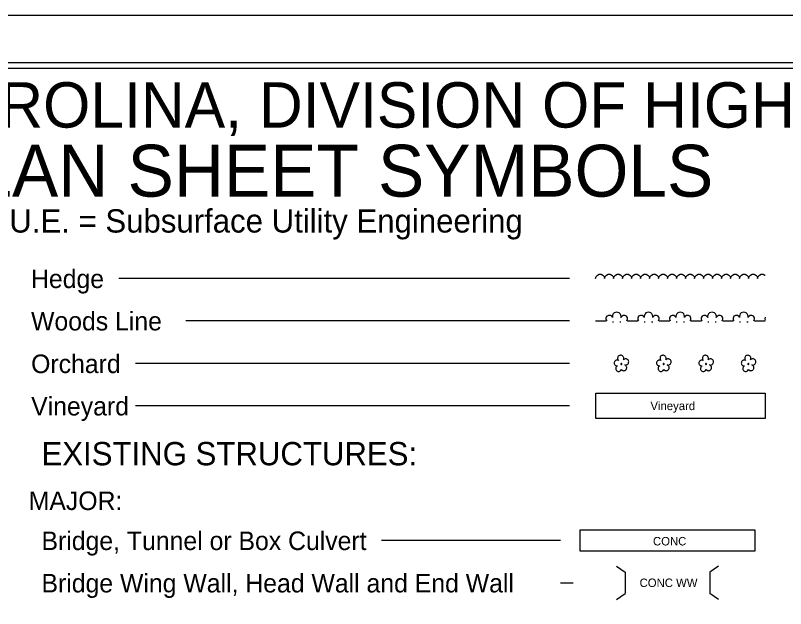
# Model space of a CAD drawing. Extents: x 1578579.3 to 1578613, y 915799 to 915821.
# Drawn here: x 1578597.74 to 1578605.02, y 915815.36 to 915820.96 of the extents above; entities that cross this region are included whole.
import ezdxf

# ---------------------------------------------------------------- set-up
doc = ezdxf.new("R2010")
doc.units = 0
for name, color, linetype in [('Sheet Cutting Line CELL', 7, 'Continuous'), ('Sheet Plot Border Inside CELL', 7, 'Continuous'), ('Sheet Plot Border Outside CELL', 7, 'Continuous'), ('Sheet Symbology CELL', 7, 'Continuous')]:
    doc.layers.add(name, color=color, linetype=linetype)

msp = doc.modelspace()

# ---------------------------------------------------------------- linework, layer by layer
at = {"layer": 'Sheet Cutting Line CELL'}
msp.add_line((1578612.9696, 915820.9627), (1578579.2896, 915820.9627), dxfattribs=at)
at = {"layer": 'Sheet Plot Border Inside CELL'}
msp.add_lwpolyline([(1578579.5496, 915799.4117), (1578612.8796, 915799.4117), (1578612.8796, 915820.5137), (1578579.5496, 915820.5137)], close=True, dxfattribs=at)
at = {"layer": 'Sheet Plot Border Outside CELL'}
msp.add_lwpolyline([(1578579.2896, 915798.9627), (1578612.9696, 915798.9627), (1578612.9696, 915820.9627), (1578579.2896, 915820.9627)], close=True, dxfattribs=at)
at = {"layer": 'Sheet Symbology CELL'}
for p, q in [((1578602.9751, 915818.4797), (1578598.7214, 915818.4797)), ((1578603.223, 915818.4797), (1578603.229, 915818.4987)), ((1578603.229, 915818.4987), (1578603.241, 915818.5117)), ((1578603.241, 915818.5117), (1578603.257, 915818.5207)), ((1578603.257, 915818.5207), (1578603.276, 915818.5207)), ((1578603.276, 915818.5207), (1578603.292, 915818.5107)), ((1578603.292, 915818.5107), (1578603.303, 915818.4977)), ((1578603.303, 915818.4977), (1578603.307, 915818.4807)), ((1578603.308, 915818.4797), (1578603.314, 915818.4987)), ((1578603.314, 915818.4987), (1578603.326, 915818.5117)), ((1578603.326, 915818.5117), (1578603.342, 915818.5207)), ((1578603.342, 915818.5207), (1578603.361, 915818.5207)), ((1578603.361, 915818.5207), (1578603.377, 915818.5107)), ((1578603.377, 915818.5107), (1578603.388, 915818.4977)), ((1578603.388, 915818.4977), (1578603.392, 915818.4807)), ((1578603.393, 915818.4797), (1578603.399, 915818.4987)), ((1578603.399, 915818.4987), (1578603.411, 915818.5117)), ((1578603.411, 915818.5117), (1578603.427, 915818.5207)), ((1578603.427, 915818.5207), (1578603.446, 915818.5207)), ((1578603.446, 915818.5207), (1578603.462, 915818.5107)), ((1578603.462, 915818.5107), (1578603.473, 915818.4977)), ((1578603.473, 915818.4977), (1578603.477, 915818.4807)), ((1578603.478, 915818.4797), (1578603.484, 915818.4987)), ((1578603.484, 915818.4987), (1578603.496, 915818.5117)), ((1578603.496, 915818.5117), (1578603.512, 915818.5207)), ((1578603.512, 915818.5207), (1578603.531, 915818.5207)), ((1578603.531, 915818.5207), (1578603.547, 915818.5107)), ((1578603.547, 915818.5107), (1578603.558, 915818.4977)), ((1578603.558, 915818.4977), (1578603.562, 915818.4807)), ((1578603.563, 915818.4797), (1578603.569, 915818.4987)), ((1578603.569, 915818.4987), (1578603.581, 915818.5117)), ((1578603.581, 915818.5117), (1578603.597, 915818.5207)), ((1578603.597, 915818.5207), (1578603.616, 915818.5207)), ((1578603.616, 915818.5207), (1578603.632, 915818.5107)), ((1578603.632, 915818.5107), (1578603.643, 915818.4977)), ((1578603.643, 915818.4977), (1578603.647, 915818.4807)), ((1578603.648, 915818.4797), (1578603.654, 915818.4987)), ((1578603.654, 915818.4987), (1578603.666, 915818.5117)), ((1578603.666, 915818.5117), (1578603.682, 915818.5207)), ((1578603.682, 915818.5207), (1578603.701, 915818.5207)), ((1578603.701, 915818.5207), (1578603.717, 915818.5107)), ((1578603.717, 915818.5107), (1578603.728, 915818.4977)), ((1578603.728, 915818.4977), (1578603.732, 915818.4807)), ((1578603.733, 915818.4797), (1578603.739, 915818.4987)), ((1578603.739, 915818.4987), (1578603.751, 915818.5117)), ((1578603.751, 915818.5117), (1578603.767, 915818.5207)), ((1578603.767, 915818.5207), (1578603.786, 915818.5207)), ((1578603.786, 915818.5207), (1578603.802, 915818.5107)), ((1578603.802, 915818.5107), (1578603.813, 915818.4977)), ((1578603.813, 915818.4977), (1578603.817, 915818.4807)), ((1578603.818, 915818.4797), (1578603.824, 915818.4987)), ((1578603.824, 915818.4987), (1578603.836, 915818.5117)), ((1578603.836, 915818.5117), (1578603.852, 915818.5207)), ((1578603.852, 915818.5207), (1578603.871, 915818.5207)), ((1578603.871, 915818.5207), (1578603.887, 915818.5107)), ((1578603.887, 915818.5107), (1578603.898, 915818.4977)), ((1578603.898, 915818.4977), (1578603.902, 915818.4807)), ((1578603.903, 915818.4797), (1578603.909, 915818.4987)), ((1578603.909, 915818.4987), (1578603.921, 915818.5117)), ((1578603.921, 915818.5117), (1578603.937, 915818.5207)), ((1578603.937, 915818.5207), (1578603.956, 915818.5207)), ((1578603.956, 915818.5207), (1578603.972, 915818.5107)), ((1578603.972, 915818.5107), (1578603.983, 915818.4977)), ((1578603.983, 915818.4977), (1578603.987, 915818.4807)), ((1578603.988, 915818.4797), (1578603.994, 915818.4987)), ((1578603.994, 915818.4987), (1578604.006, 915818.5117)), ((1578604.006, 915818.5117), (1578604.022, 915818.5207)), ((1578604.022, 915818.5207), (1578604.041, 915818.5207)), ((1578604.041, 915818.5207), (1578604.057, 915818.5107)), ((1578604.057, 915818.5107), (1578604.068, 915818.4977)), ((1578604.068, 915818.4977), (1578604.072, 915818.4807)), ((1578604.073, 915818.4797), (1578604.079, 915818.4987)), ((1578604.079, 915818.4987), (1578604.091, 915818.5117)), ((1578604.091, 915818.5117), (1578604.107, 915818.5207)), ((1578604.107, 915818.5207), (1578604.126, 915818.5207)), ((1578604.126, 915818.5207), (1578604.142, 915818.5107)), ((1578604.142, 915818.5107), (1578604.153, 915818.4977)), ((1578604.153, 915818.4977), (1578604.157, 915818.4807)), ((1578604.158, 915818.4797), (1578604.164, 915818.4987)), ((1578604.164, 915818.4987), (1578604.176, 915818.5117)), ((1578604.176, 915818.5117), (1578604.192, 915818.5207)), ((1578604.192, 915818.5207), (1578604.211, 915818.5207)), ((1578604.211, 915818.5207), (1578604.227, 915818.5107)), ((1578604.227, 915818.5107), (1578604.238, 915818.4977)), ((1578604.238, 915818.4977), (1578604.242, 915818.4807)), ((1578604.243, 915818.4797), (1578604.249, 915818.4987)), ((1578604.249, 915818.4987), (1578604.261, 915818.5117)), ((1578604.261, 915818.5117), (1578604.277, 915818.5207)), ((1578604.277, 915818.5207), (1578604.296, 915818.5207)), ((1578604.296, 915818.5207), (1578604.312, 915818.5107)), ((1578604.312, 915818.5107), (1578604.323, 915818.4977)), ((1578604.323, 915818.4977), (1578604.327, 915818.4807)), ((1578604.328, 915818.4797), (1578604.334, 915818.4987)), ((1578604.334, 915818.4987), (1578604.346, 915818.5117)), ((1578604.346, 915818.5117), (1578604.362, 915818.5207)), ((1578604.362, 915818.5207), (1578604.381, 915818.5207)), ((1578604.381, 915818.5207), (1578604.397, 915818.5107)), ((1578604.397, 915818.5107), (1578604.408, 915818.4977)), ((1578604.408, 915818.4977), (1578604.412, 915818.4807)), ((1578604.413, 915818.4797), (1578604.419, 915818.4987)), ((1578604.419, 915818.4987), (1578604.431, 915818.5117)), ((1578604.431, 915818.5117), (1578604.447, 915818.5207)), ((1578604.447, 915818.5207), (1578604.466, 915818.5207)), ((1578604.466, 915818.5207), (1578604.482, 915818.5107)), ((1578604.482, 915818.5107), (1578604.493, 915818.4977)), ((1578604.493, 915818.4977), (1578604.497, 915818.4807)), ((1578604.498, 915818.4797), (1578604.504, 915818.4987)), ((1578604.504, 915818.4987), (1578604.516, 915818.5117)), ((1578604.516, 915818.5117), (1578604.532, 915818.5207)), ((1578604.532, 915818.5207), (1578604.551, 915818.5207)), ((1578604.551, 915818.5207), (1578604.567, 915818.5107)), ((1578604.567, 915818.5107), (1578604.578, 915818.4977)), ((1578604.578, 915818.4977), (1578604.582, 915818.4807)), ((1578604.583, 915818.4797), (1578604.589, 915818.4987)), ((1578604.589, 915818.4987), (1578604.601, 915818.5117)), ((1578604.601, 915818.5117), (1578604.617, 915818.5207)), ((1578604.617, 915818.5207), (1578604.636, 915818.5207)), ((1578604.636, 915818.5207), (1578604.652, 915818.5107)), ((1578604.652, 915818.5107), (1578604.663, 915818.4977)), ((1578604.663, 915818.4977), (1578604.667, 915818.4807)), ((1578604.668, 915818.4797), (1578604.674, 915818.4987)), ((1578604.674, 915818.4987), (1578604.686, 915818.5117)), ((1578604.686, 915818.5117), (1578604.702, 915818.5207)), ((1578604.702, 915818.5207), (1578604.721, 915818.5207)), ((1578604.721, 915818.5207), (1578604.737, 915818.5107)), ((1578604.737, 915818.5107), (1578604.748, 915818.4977)), ((1578604.748, 915818.4977), (1578604.752, 915818.4807)), ((1578604.753, 915818.4797), (1578604.759, 915818.4987)), ((1578604.759, 915818.4987), (1578604.771, 915818.5117)), ((1578604.771, 915818.5117), (1578604.787, 915818.5207)), ((1578604.787, 915818.5207), (1578604.806, 915818.5207)), ((1578604.806, 915818.5207), (1578604.822, 915818.5107)), ((1578604.822, 915818.5107), (1578604.823, 915818.5097)), ((1578602.9751, 915818.0797), (1578599.3526, 915818.0797)), ((1578603.223, 915818.0797), (1578603.323, 915818.0797)), ((1578603.382, 915818.0697), (1578603.392, 915818.0697)), ((1578603.452, 915818.0697), (1578603.462, 915818.0697)), ((1578603.523, 915818.0797), (1578603.623, 915818.0797)), ((1578603.682, 915818.0697), (1578603.692, 915818.0697)), ((1578603.752, 915818.0697), (1578603.762, 915818.0697)), ((1578603.823, 915818.0797), (1578603.923, 915818.0797)), ((1578603.982, 915818.0697), (1578603.992, 915818.0697)), ((1578604.052, 915818.0697), (1578604.062, 915818.0697)), ((1578604.123, 915818.0797), (1578604.223, 915818.0797)), ((1578604.282, 915818.0697), (1578604.292, 915818.0697)), ((1578604.352, 915818.0697), (1578604.362, 915818.0697)), ((1578604.423, 915818.0797), (1578604.523, 915818.0797)), ((1578604.582, 915818.0697), (1578604.592, 915818.0697)), ((1578604.652, 915818.0697), (1578604.662, 915818.0697)), ((1578604.723, 915818.0797), (1578604.823, 915818.0797)), ((1578602.9761, 915817.677), (1578598.8774, 915817.677)), ((1578602.9761, 915817.277), (1578598.8774, 915817.277)), ((1578602.8898, 915816.0069), (1578601.2013, 915816.0069)), ((1578603.4188, 915815.7641), (1578603.5008, 915815.7069)), ((1578603.5008, 915815.7069), (1578603.5008, 915815.5069)), ((1578604.3828, 915815.7641), (1578604.3008, 915815.7069)), ((1578604.3008, 915815.7069), (1578604.3008, 915815.5069)), ((1578602.8898, 915815.6069), (1578603.0096, 915815.6069)), ((1578603.4188, 915815.4496), (1578603.5008, 915815.5069)), ((1578604.3828, 915815.4496), (1578604.3008, 915815.5069))]:
    msp.add_line(p, q, dxfattribs=at)
msp.add_lwpolyline([(1578612.6296, 915820.4627), (1578582.6296, 915820.4627), (1578582.6296, 915799.483), (1578612.6296, 915799.483)], close=True, dxfattribs=at)
for points in [[(1578603.485, 915817.712), (1578603.488, 915817.718), (1578603.489, 915817.724), (1578603.488, 915817.73), (1578603.487, 915817.736), (1578603.484, 915817.741), (1578603.481, 915817.746), (1578603.476, 915817.75), (1578603.471, 915817.753), (1578603.464, 915817.755), (1578603.459, 915817.755), (1578603.453, 915817.754), (1578603.447, 915817.752), (1578603.442, 915817.749), (1578603.437, 915817.745), (1578603.434, 915817.739), (1578603.432, 915817.734), (1578603.431, 915817.728), (1578603.431, 915817.722), (1578603.432, 915817.716), (1578603.435, 915817.711), (1578603.439, 915817.705), (1578603.434, 915817.708), (1578603.428, 915817.709), (1578603.422, 915817.709), (1578603.417, 915817.707), (1578603.412, 915817.705), (1578603.407, 915817.701), (1578603.403, 915817.697), (1578603.4, 915817.692), (1578603.399, 915817.687), (1578603.398, 915817.68), (1578603.399, 915817.675), (1578603.401, 915817.67), (1578603.405, 915817.665), (1578603.408, 915817.661), (1578603.413, 915817.658), (1578603.419, 915817.655), (1578603.424, 915817.654), (1578603.43, 915817.654), (1578603.425, 915817.652), (1578603.42, 915817.648), (1578603.417, 915817.644), (1578603.415, 915817.638), (1578603.413, 915817.632), (1578603.413, 915817.627), (1578603.414, 915817.621), (1578603.417, 915817.616), (1578603.42, 915817.611), (1578603.424, 915817.607), (1578603.429, 915817.604), (1578603.434, 915817.602), (1578603.44, 915817.602), (1578603.446, 915817.602), (1578603.451, 915817.603), (1578603.456, 915817.607), (1578603.461, 915817.61), (1578603.466, 915817.619)], [(1578603.885, 915817.712), (1578603.888, 915817.718), (1578603.889, 915817.724), (1578603.888, 915817.73), (1578603.887, 915817.736), (1578603.884, 915817.741), (1578603.881, 915817.746), (1578603.876, 915817.75), (1578603.871, 915817.753), (1578603.864, 915817.755), (1578603.859, 915817.755), (1578603.853, 915817.754), (1578603.847, 915817.752), (1578603.842, 915817.749), (1578603.837, 915817.745), (1578603.834, 915817.739), (1578603.832, 915817.734), (1578603.831, 915817.728), (1578603.831, 915817.722), (1578603.832, 915817.716), (1578603.835, 915817.711), (1578603.839, 915817.705), (1578603.834, 915817.708), (1578603.828, 915817.709), (1578603.822, 915817.709), (1578603.817, 915817.707), (1578603.812, 915817.705), (1578603.807, 915817.701), (1578603.803, 915817.697), (1578603.8, 915817.692), (1578603.799, 915817.687), (1578603.798, 915817.68), (1578603.799, 915817.675), (1578603.801, 915817.67), (1578603.805, 915817.665), (1578603.808, 915817.661), (1578603.813, 915817.658), (1578603.819, 915817.655), (1578603.824, 915817.654), (1578603.83, 915817.654), (1578603.825, 915817.652), (1578603.82, 915817.648), (1578603.817, 915817.644), (1578603.815, 915817.638), (1578603.813, 915817.632), (1578603.813, 915817.627), (1578603.814, 915817.621), (1578603.817, 915817.616), (1578603.82, 915817.611), (1578603.824, 915817.607), (1578603.829, 915817.604), (1578603.834, 915817.602), (1578603.84, 915817.602), (1578603.846, 915817.602), (1578603.851, 915817.603), (1578603.856, 915817.607), (1578603.861, 915817.61), (1578603.866, 915817.619)], [(1578604.285, 915817.712), (1578604.288, 915817.718), (1578604.289, 915817.724), (1578604.288, 915817.73), (1578604.287, 915817.736), (1578604.284, 915817.741), (1578604.281, 915817.746), (1578604.276, 915817.75), (1578604.271, 915817.753), (1578604.264, 915817.755), (1578604.259, 915817.755), (1578604.253, 915817.754), (1578604.247, 915817.752), (1578604.242, 915817.749), (1578604.237, 915817.745), (1578604.234, 915817.739), (1578604.232, 915817.734), (1578604.231, 915817.728), (1578604.231, 915817.722), (1578604.232, 915817.716), (1578604.235, 915817.711), (1578604.239, 915817.705), (1578604.234, 915817.708), (1578604.228, 915817.709), (1578604.222, 915817.709), (1578604.217, 915817.707), (1578604.212, 915817.705), (1578604.207, 915817.701), (1578604.203, 915817.697), (1578604.2, 915817.692), (1578604.199, 915817.687), (1578604.198, 915817.68), (1578604.199, 915817.675), (1578604.201, 915817.67), (1578604.205, 915817.665), (1578604.208, 915817.661), (1578604.213, 915817.658), (1578604.219, 915817.655), (1578604.224, 915817.654), (1578604.23, 915817.654), (1578604.225, 915817.652), (1578604.22, 915817.648), (1578604.217, 915817.644), (1578604.215, 915817.638), (1578604.213, 915817.632), (1578604.213, 915817.627), (1578604.214, 915817.621), (1578604.217, 915817.616), (1578604.22, 915817.611), (1578604.224, 915817.607), (1578604.229, 915817.604), (1578604.234, 915817.602), (1578604.24, 915817.602), (1578604.246, 915817.602), (1578604.251, 915817.603), (1578604.256, 915817.607), (1578604.261, 915817.61), (1578604.266, 915817.619)], [(1578604.685, 915817.712), (1578604.688, 915817.718), (1578604.689, 915817.724), (1578604.688, 915817.73), (1578604.687, 915817.736), (1578604.684, 915817.741), (1578604.681, 915817.746), (1578604.676, 915817.75), (1578604.671, 915817.753), (1578604.664, 915817.755), (1578604.659, 915817.755), (1578604.653, 915817.754), (1578604.647, 915817.752), (1578604.642, 915817.749), (1578604.637, 915817.745), (1578604.634, 915817.739), (1578604.632, 915817.734), (1578604.631, 915817.728), (1578604.631, 915817.722), (1578604.632, 915817.716), (1578604.635, 915817.711), (1578604.639, 915817.705), (1578604.634, 915817.708), (1578604.628, 915817.709), (1578604.622, 915817.709), (1578604.617, 915817.707), (1578604.612, 915817.705), (1578604.607, 915817.701), (1578604.603, 915817.697), (1578604.6, 915817.692), (1578604.599, 915817.687), (1578604.598, 915817.68), (1578604.599, 915817.675), (1578604.601, 915817.67), (1578604.605, 915817.665), (1578604.608, 915817.661), (1578604.613, 915817.658), (1578604.619, 915817.655), (1578604.624, 915817.654), (1578604.63, 915817.654), (1578604.625, 915817.652), (1578604.62, 915817.648), (1578604.617, 915817.644), (1578604.615, 915817.638), (1578604.613, 915817.632), (1578604.613, 915817.627), (1578604.614, 915817.621), (1578604.617, 915817.616), (1578604.62, 915817.611), (1578604.624, 915817.607), (1578604.629, 915817.604), (1578604.634, 915817.602), (1578604.64, 915817.602), (1578604.646, 915817.602), (1578604.651, 915817.603), (1578604.656, 915817.607), (1578604.661, 915817.61), (1578604.666, 915817.619)], [(1578603.468, 915817.677), (1578603.465, 915817.677), (1578603.463, 915817.676), (1578603.461, 915817.675), (1578603.461, 915817.672), (1578603.461, 915817.67), (1578603.463, 915817.668), (1578603.466, 915817.668), (1578603.468, 915817.668), (1578603.47, 915817.67), (1578603.471, 915817.673), (1578603.47, 915817.675), (1578603.468, 915817.677)], [(1578603.466, 915817.619), (1578603.478, 915817.612), (1578603.484, 915817.61), (1578603.49, 915817.609), (1578603.496, 915817.61), (1578603.501, 915817.612), (1578603.506, 915817.615), (1578603.511, 915817.619), (1578603.514, 915817.624), (1578603.516, 915817.629), (1578603.518, 915817.635), (1578603.517, 915817.641), (1578603.516, 915817.647), (1578603.512, 915817.653), (1578603.509, 915817.657), (1578603.504, 915817.66), (1578603.498, 915817.663), (1578603.504, 915817.662), (1578603.511, 915817.662), (1578603.516, 915817.664), (1578603.522, 915817.667), (1578603.527, 915817.67), (1578603.531, 915817.675), (1578603.534, 915817.681), (1578603.535, 915817.687), (1578603.536, 915817.693), (1578603.535, 915817.699), (1578603.533, 915817.705), (1578603.529, 915817.71), (1578603.524, 915817.715), (1578603.519, 915817.718), (1578603.513, 915817.72), (1578603.507, 915817.721), (1578603.501, 915817.721), (1578603.495, 915817.719), (1578603.49, 915817.716), (1578603.485, 915817.712)], [(1578603.868, 915817.677), (1578603.865, 915817.677), (1578603.863, 915817.676), (1578603.861, 915817.675), (1578603.861, 915817.672), (1578603.861, 915817.67), (1578603.863, 915817.668), (1578603.866, 915817.668), (1578603.868, 915817.668), (1578603.87, 915817.67), (1578603.871, 915817.673), (1578603.87, 915817.675), (1578603.868, 915817.677)], [(1578603.866, 915817.619), (1578603.878, 915817.612), (1578603.884, 915817.61), (1578603.89, 915817.609), (1578603.896, 915817.61), (1578603.901, 915817.612), (1578603.906, 915817.615), (1578603.911, 915817.619), (1578603.914, 915817.624), (1578603.916, 915817.629), (1578603.918, 915817.635), (1578603.917, 915817.641), (1578603.916, 915817.647), (1578603.912, 915817.653), (1578603.909, 915817.657), (1578603.904, 915817.66), (1578603.898, 915817.663), (1578603.904, 915817.662), (1578603.911, 915817.662), (1578603.916, 915817.664), (1578603.922, 915817.667), (1578603.927, 915817.67), (1578603.931, 915817.675), (1578603.934, 915817.681), (1578603.935, 915817.687), (1578603.936, 915817.693), (1578603.935, 915817.699), (1578603.933, 915817.705), (1578603.929, 915817.71), (1578603.924, 915817.715), (1578603.919, 915817.718), (1578603.913, 915817.72), (1578603.907, 915817.721), (1578603.901, 915817.721), (1578603.895, 915817.719), (1578603.89, 915817.716), (1578603.885, 915817.712)], [(1578604.268, 915817.677), (1578604.265, 915817.677), (1578604.263, 915817.676), (1578604.261, 915817.675), (1578604.261, 915817.672), (1578604.261, 915817.67), (1578604.263, 915817.668), (1578604.266, 915817.668), (1578604.268, 915817.668), (1578604.27, 915817.67), (1578604.271, 915817.673), (1578604.27, 915817.675), (1578604.268, 915817.677)], [(1578604.266, 915817.619), (1578604.278, 915817.612), (1578604.284, 915817.61), (1578604.29, 915817.609), (1578604.296, 915817.61), (1578604.301, 915817.612), (1578604.306, 915817.615), (1578604.311, 915817.619), (1578604.314, 915817.624), (1578604.316, 915817.629), (1578604.318, 915817.635), (1578604.317, 915817.641), (1578604.316, 915817.647), (1578604.312, 915817.653), (1578604.309, 915817.657), (1578604.304, 915817.66), (1578604.298, 915817.663), (1578604.304, 915817.662), (1578604.311, 915817.662), (1578604.316, 915817.664), (1578604.322, 915817.667), (1578604.327, 915817.67), (1578604.331, 915817.675), (1578604.334, 915817.681), (1578604.335, 915817.687), (1578604.336, 915817.693), (1578604.335, 915817.699), (1578604.333, 915817.705), (1578604.329, 915817.71), (1578604.324, 915817.715), (1578604.319, 915817.718), (1578604.313, 915817.72), (1578604.307, 915817.721), (1578604.301, 915817.721), (1578604.295, 915817.719), (1578604.29, 915817.716), (1578604.285, 915817.712)], [(1578604.668, 915817.677), (1578604.665, 915817.677), (1578604.663, 915817.676), (1578604.661, 915817.675), (1578604.661, 915817.672), (1578604.661, 915817.67), (1578604.663, 915817.668), (1578604.666, 915817.668), (1578604.668, 915817.668), (1578604.67, 915817.67), (1578604.671, 915817.673), (1578604.67, 915817.675), (1578604.668, 915817.677)], [(1578604.666, 915817.619), (1578604.678, 915817.612), (1578604.684, 915817.61), (1578604.69, 915817.609), (1578604.696, 915817.61), (1578604.701, 915817.612), (1578604.706, 915817.615), (1578604.711, 915817.619), (1578604.714, 915817.624), (1578604.716, 915817.629), (1578604.718, 915817.635), (1578604.717, 915817.641), (1578604.716, 915817.647), (1578604.712, 915817.653), (1578604.709, 915817.657), (1578604.704, 915817.66), (1578604.698, 915817.663), (1578604.704, 915817.662), (1578604.711, 915817.662), (1578604.716, 915817.664), (1578604.722, 915817.667), (1578604.727, 915817.67), (1578604.731, 915817.675), (1578604.734, 915817.681), (1578604.735, 915817.687), (1578604.736, 915817.693), (1578604.735, 915817.699), (1578604.733, 915817.705), (1578604.729, 915817.71), (1578604.724, 915817.715), (1578604.719, 915817.718), (1578604.713, 915817.72), (1578604.707, 915817.721), (1578604.701, 915817.721), (1578604.695, 915817.719), (1578604.69, 915817.716), (1578604.685, 915817.712)], [(1578603.224, 915817.397), (1578604.824, 915817.397), (1578604.824, 915817.157), (1578603.224, 915817.157), (1578603.224, 915817.397)], [(1578603.0758, 915816.1069), (1578604.7258, 915816.1069), (1578604.7258, 915815.9069), (1578603.0758, 915815.9069), (1578603.0758, 915816.1069)]]:
    msp.add_lwpolyline(points, dxfattribs=at)
for centre, radius, start, end in [((1578603.352, 915818.1), 0.0316, 18.43495, 219.23152), ((1578603.422, 915818.12), 0.0412, 345.96376, 194.03624), ((1578603.492, 915818.1), 0.0316, 320.76848, 161.56505), ((1578603.6519, 915818.1), 0.0316, 18.43495, 219.23152), ((1578603.7219, 915818.12), 0.0412, 345.96376, 194.03624), ((1578603.7919, 915818.1), 0.0316, 320.76848, 161.56505), ((1578603.9519, 915818.1), 0.0316, 18.43495, 219.23152), ((1578604.0219, 915818.12), 0.0412, 345.96376, 194.03624), ((1578604.0919, 915818.1), 0.0316, 320.76848, 161.56505), ((1578604.2519, 915818.1), 0.0316, 18.43495, 219.23152), ((1578604.3219, 915818.12), 0.0412, 345.96376, 194.03624), ((1578604.3919, 915818.1), 0.0316, 320.76848, 161.56505), ((1578604.5519, 915818.1), 0.0316, 18.43495, 219.23152), ((1578604.6219, 915818.12), 0.0412, 345.96376, 194.03624), ((1578604.6919, 915818.1), 0.0316, 320.76848, 161.56505), ((1578604.8519, 915818.1), 0.0316, 156.25102, 203.74899)]:
    msp.add_arc(centre, radius, start, end, dxfattribs=at)

# ---------------------------------------------------------------- texts
for s, height, p in [('STATE OF NORTH CAROLINA, DIVISION OF HIGHWAYS', 0.42838, (1578591.6408, 915819.9035)), ('CONVENTIONAL  PLAN SHEET SYMBOLS', 0.489606, (1578591.3818, 915819.2521)), ('Hedge', 0.175, (1578597.8919, 915818.3892)), ('Woods Line', 0.175, (1578597.8919, 915817.9892)), ('Orchard', 0.175, (1578597.8929, 915817.5865)), ('Vineyard', 0.175, (1578597.8929, 915817.1865)), ('EXISTING STRUCTURES:', 0.220001, (1578597.9906, 915816.7159)), ('MAJOR:', 0.175, (1578597.8701, 915816.2936)), ('Bridge, Tunnel or Box Culvert', 0.175001, (1578597.9906, 915815.9159)), ('CONC', 0.08, (1578603.7646, 915815.9596)), ('Bridge Wing Wall, Head Wall and End Wall', 0.175001, (1578597.9906, 915815.5159))]:
    msp.add_text(s, height=height, dxfattribs=at).set_placement(p)
for s, height, rotation, p in [('*S.U.E. = Subsurface Utility Engineering', 0.220001, 360, (1578597.2939, 915818.9129)), ('Vineyard', 0.08, 0.00002, (1578603.7405, 915817.237)), ('CONC WW', 0.08, 0.00002, (1578603.6383, 915815.5669))]:
    msp.add_text(s, height=height, rotation=rotation, dxfattribs=at).set_placement(p)

doc.saveas('drawing.dxf')
